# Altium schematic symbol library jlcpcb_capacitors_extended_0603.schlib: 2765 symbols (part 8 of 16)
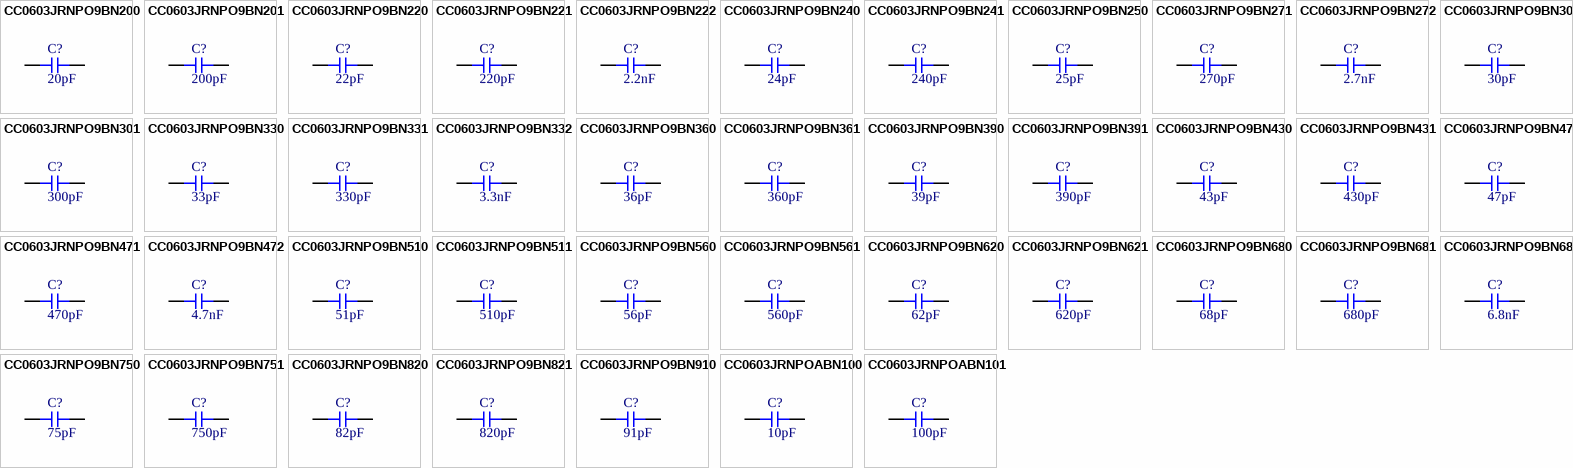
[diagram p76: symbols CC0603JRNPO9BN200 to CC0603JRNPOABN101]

## CC0603JRNPO9BN221
designator C?  Capacitance: 220pF  (hidden comment: *)
Capacitor, Ceramic (MLCC), 220pF, ±5%, 50V, NP0, ±5%, SMD 0603; Manufacturer: YAGEO; Manufacturer Part Number: CC0603JRNPO9BN221
footprint CAP-0603 (0603 (1608M) Capacitor)
pins: 1, 2

## CC0603JRNPO9BN222
designator C?  Capacitance: 2.2nF  (hidden comment: *)
Capacitor, Ceramic (MLCC), 2.2nF, ±5%, 50V, NP0, ±5%, SMD 0603; Manufacturer: YAGEO; Manufacturer Part Number: CC0603JRNPO9BN222
footprint CAP-0603 (0603 (1608M) Capacitor)
pins: 1, 2

## CC0603JRNPO9BN240
designator C?  Capacitance: 24pF  (hidden comment: *)
Capacitor, Ceramic (MLCC), 24pF, ±5%, 50V, NP0, ±5%, SMD 0603; Manufacturer: YAGEO; Manufacturer Part Number: CC0603JRNPO9BN240
footprint CAP-0603 (0603 (1608M) Capacitor)
pins: 1, 2

## CC0603JRNPO9BN241
designator C?  Capacitance: 240pF  (hidden comment: *)
Capacitor, Ceramic (MLCC), 240pF, ±5%, 50V, NP0, ±5%, SMD 0603; Manufacturer: YAGEO; Manufacturer Part Number: CC0603JRNPO9BN241
footprint CAP-0603 (0603 (1608M) Capacitor)
pins: 1, 2

## CC0603JRNPO9BN250
designator C?  Capacitance: 25pF  (hidden comment: *)
Capacitor, Ceramic (MLCC), 25pF, ±5%, 50V, NP0, ±5%, SMD 0603; Manufacturer: YAGEO; Manufacturer Part Number: CC0603JRNPO9BN250
footprint CAP-0603 (0603 (1608M) Capacitor)
pins: 1, 2

## CC0603JRNPO9BN271
designator C?  Capacitance: 270pF  (hidden comment: *)
Capacitor, Ceramic (MLCC), 270pF, ±5%, 50V, NP0, ±5%, SMD 0603; Manufacturer: YAGEO; Manufacturer Part Number: CC0603JRNPO9BN271
footprint CAP-0603 (0603 (1608M) Capacitor)
pins: 1, 2

## CC0603JRNPO9BN272
designator C?  Capacitance: 2.7nF  (hidden comment: *)
Capacitor, Ceramic (MLCC), 2.7nF, ±5%, 50V, NP0, ±5%, SMD 0603; Manufacturer: YAGEO; Manufacturer Part Number: CC0603JRNPO9BN272
footprint CAP-0603 (0603 (1608M) Capacitor)
pins: 1, 2

## CC0603JRNPO9BN300
designator C?  Capacitance: 30pF  (hidden comment: *)
Capacitor, Ceramic (MLCC), 30pF, ±5%, 50V, NP0, ±5%, SMD 0603; Manufacturer: YAGEO; Manufacturer Part Number: CC0603JRNPO9BN300
footprint CAP-0603 (0603 (1608M) Capacitor)
pins: 1, 2

## CC0603JRNPO9BN301
designator C?  Capacitance: 300pF  (hidden comment: *)
Capacitor, Ceramic (MLCC), 300pF, ±5%, 50V, NP0, ±5%, SMD 0603; Manufacturer: YAGEO; Manufacturer Part Number: CC0603JRNPO9BN301
footprint CAP-0603 (0603 (1608M) Capacitor)
pins: 1, 2

## CC0603JRNPO9BN330
designator C?  Capacitance: 33pF  (hidden comment: *)
Capacitor, Ceramic (MLCC), 33pF, ±5%, 50V, NP0, ±5%, SMD 0603; Manufacturer: YAGEO; Manufacturer Part Number: CC0603JRNPO9BN330
footprint CAP-0603 (0603 (1608M) Capacitor)
pins: 1, 2

## CC0603JRNPO9BN331
designator C?  Capacitance: 330pF  (hidden comment: *)
Capacitor, Ceramic (MLCC), 330pF, ±5%, 50V, NP0, ±5%, SMD 0603; Manufacturer: YAGEO; Manufacturer Part Number: CC0603JRNPO9BN331
footprint CAP-0603 (0603 (1608M) Capacitor)
pins: 1, 2

## CC0603JRNPO9BN332
designator C?  Capacitance: 3.3nF  (hidden comment: *)
Capacitor, Ceramic (MLCC), 3.3nF, ±5%, 50V, NP0, ±5%, SMD 0603; Manufacturer: YAGEO; Manufacturer Part Number: CC0603JRNPO9BN332
footprint CAP-0603 (0603 (1608M) Capacitor)
pins: 1, 2

## CC0603JRNPO9BN360
designator C?  Capacitance: 36pF  (hidden comment: *)
Capacitor, Ceramic (MLCC), 36pF, ±5%, 50V, NP0, ±5%, SMD 0603; Manufacturer: YAGEO; Manufacturer Part Number: CC0603JRNPO9BN360
footprint CAP-0603 (0603 (1608M) Capacitor)
pins: 1, 2

## CC0603JRNPO9BN361
designator C?  Capacitance: 360pF  (hidden comment: *)
Capacitor, Ceramic (MLCC), 360pF, ±5%, 50V, NP0, ±5%, SMD 0603; Manufacturer: YAGEO; Manufacturer Part Number: CC0603JRNPO9BN361
footprint CAP-0603 (0603 (1608M) Capacitor)
pins: 1, 2

## CC0603JRNPO9BN390
designator C?  Capacitance: 39pF  (hidden comment: *)
Capacitor, Ceramic (MLCC), 39pF, ±5%, 50V, NP0, ±5%, SMD 0603; Manufacturer: YAGEO; Manufacturer Part Number: CC0603JRNPO9BN390
footprint CAP-0603 (0603 (1608M) Capacitor)
pins: 1, 2

## CC0603JRNPO9BN391
designator C?  Capacitance: 390pF  (hidden comment: *)
Capacitor, Ceramic (MLCC), 390pF, ±5%, 50V, NP0, ±5%, SMD 0603; Manufacturer: YAGEO; Manufacturer Part Number: CC0603JRNPO9BN391
footprint CAP-0603 (0603 (1608M) Capacitor)
pins: 1, 2

## CC0603JRNPO9BN430
designator C?  Capacitance: 43pF  (hidden comment: *)
Capacitor, Ceramic (MLCC), 43pF, ±5%, 50V, NP0, ±5%, SMD 0603; Manufacturer: YAGEO; Manufacturer Part Number: CC0603JRNPO9BN430
footprint CAP-0603 (0603 (1608M) Capacitor)
pins: 1, 2

## CC0603JRNPO9BN431
designator C?  Capacitance: 430pF  (hidden comment: *)
Capacitor, Ceramic (MLCC), 430pF, ±5%, 50V, NP0, ±5%, SMD 0603; Manufacturer: YAGEO; Manufacturer Part Number: CC0603JRNPO9BN431
footprint CAP-0603 (0603 (1608M) Capacitor)
pins: 1, 2

## CC0603JRNPO9BN470
designator C?  Capacitance: 47pF  (hidden comment: *)
Capacitor, Ceramic (MLCC), 47pF, ±5%, 50V, NP0, ±5%, SMD 0603; Manufacturer: YAGEO; Manufacturer Part Number: CC0603JRNPO9BN470
footprint CAP-0603 (0603 (1608M) Capacitor)
pins: 1, 2

## CC0603JRNPO9BN471
designator C?  Capacitance: 470pF  (hidden comment: *)
Capacitor, Ceramic (MLCC), 470pF, ±5%, 50V, NP0, ±5%, SMD 0603; Manufacturer: YAGEO; Manufacturer Part Number: CC0603JRNPO9BN471
footprint CAP-0603 (0603 (1608M) Capacitor)
pins: 1, 2

## CC0603JRNPO9BN472
designator C?  Capacitance: 4.7nF  (hidden comment: *)
Capacitor, Ceramic (MLCC), 4.7nF, ±5%, 50V, NP0, ±5%, SMD 0603; Manufacturer: YAGEO; Manufacturer Part Number: CC0603JRNPO9BN472
footprint CAP-0603 (0603 (1608M) Capacitor)
pins: 1, 2

## CC0603JRNPO9BN510
designator C?  Capacitance: 51pF  (hidden comment: *)
Capacitor, Ceramic (MLCC), 51pF, ±5%, 50V, NP0, ±5%, SMD 0603; Manufacturer: YAGEO; Manufacturer Part Number: CC0603JRNPO9BN510
footprint CAP-0603 (0603 (1608M) Capacitor)
pins: 1, 2

## CC0603JRNPO9BN511
designator C?  Capacitance: 510pF  (hidden comment: *)
Capacitor, Ceramic (MLCC), 510pF, ±5%, 50V, NP0, ±5%, SMD 0603; Manufacturer: YAGEO; Manufacturer Part Number: CC0603JRNPO9BN511
footprint CAP-0603 (0603 (1608M) Capacitor)
pins: 1, 2

## CC0603JRNPO9BN560
designator C?  Capacitance: 56pF  (hidden comment: *)
Capacitor, Ceramic (MLCC), 56pF, ±5%, 50V, NP0, ±5%, SMD 0603; Manufacturer: YAGEO; Manufacturer Part Number: CC0603JRNPO9BN560
footprint CAP-0603 (0603 (1608M) Capacitor)
pins: 1, 2

## CC0603JRNPO9BN561
designator C?  Capacitance: 560pF  (hidden comment: *)
Capacitor, Ceramic (MLCC), 560pF, ±5%, 50V, NP0, ±5%, SMD 0603; Manufacturer: YAGEO; Manufacturer Part Number: CC0603JRNPO9BN561
footprint CAP-0603 (0603 (1608M) Capacitor)
pins: 1, 2

## CC0603JRNPO9BN620
designator C?  Capacitance: 62pF  (hidden comment: *)
Capacitor, Ceramic (MLCC), 62pF, ±5%, 50V, NP0, ±5%, SMD 0603; Manufacturer: YAGEO; Manufacturer Part Number: CC0603JRNPO9BN620
footprint CAP-0603 (0603 (1608M) Capacitor)
pins: 1, 2

## CC0603JRNPO9BN621
designator C?  Capacitance: 620pF  (hidden comment: *)
Capacitor, Ceramic (MLCC), 620pF, ±5%, 50V, NP0, ±5%, SMD 0603; Manufacturer: YAGEO; Manufacturer Part Number: CC0603JRNPO9BN621
footprint CAP-0603 (0603 (1608M) Capacitor)
pins: 1, 2

## CC0603JRNPO9BN680
designator C?  Capacitance: 68pF  (hidden comment: *)
Capacitor, Ceramic (MLCC), 68pF, ±5%, 50V, NP0, ±5%, SMD 0603; Manufacturer: YAGEO; Manufacturer Part Number: CC0603JRNPO9BN680
footprint CAP-0603 (0603 (1608M) Capacitor)
pins: 1, 2

## CC0603JRNPO9BN681
designator C?  Capacitance: 680pF  (hidden comment: *)
Capacitor, Ceramic (MLCC), 680pF, ±5%, 50V, NP0, ±5%, SMD 0603; Manufacturer: YAGEO; Manufacturer Part Number: CC0603JRNPO9BN681
footprint CAP-0603 (0603 (1608M) Capacitor)
pins: 1, 2

## CC0603JRNPO9BN682
designator C?  Capacitance: 6.8nF  (hidden comment: *)
Capacitor, Ceramic (MLCC), 6.8nF, ±5%, 50V, NP0, ±5%, SMD 0603; Manufacturer: YAGEO; Manufacturer Part Number: CC0603JRNPO9BN682
footprint CAP-0603 (0603 (1608M) Capacitor)
pins: 1, 2

## CC0603JRNPO9BN750
designator C?  Capacitance: 75pF  (hidden comment: *)
Capacitor, Ceramic (MLCC), 75pF, ±5%, 50V, NP0, ±5%, SMD 0603; Manufacturer: YAGEO; Manufacturer Part Number: CC0603JRNPO9BN750
footprint CAP-0603 (0603 (1608M) Capacitor)
pins: 1, 2

## CC0603JRNPO9BN751
designator C?  Capacitance: 750pF  (hidden comment: *)
Capacitor, Ceramic (MLCC), 750pF, ±5%, 50V, NP0, ±5%, SMD 0603; Manufacturer: YAGEO; Manufacturer Part Number: CC0603JRNPO9BN751
footprint CAP-0603 (0603 (1608M) Capacitor)
pins: 1, 2

## CC0603JRNPO9BN820
designator C?  Capacitance: 82pF  (hidden comment: *)
Capacitor, Ceramic (MLCC), 82pF, ±5%, 50V, NP0, ±5%, SMD 0603; Manufacturer: YAGEO; Manufacturer Part Number: CC0603JRNPO9BN820
footprint CAP-0603 (0603 (1608M) Capacitor)
pins: 1, 2

## CC0603JRNPO9BN821
designator C?  Capacitance: 820pF  (hidden comment: *)
Capacitor, Ceramic (MLCC), 820pF, ±5%, 50V, NP0, ±5%, SMD 0603; Manufacturer: YAGEO; Manufacturer Part Number: CC0603JRNPO9BN821
footprint CAP-0603 (0603 (1608M) Capacitor)
pins: 1, 2

## CC0603JRNPO9BN910
designator C?  Capacitance: 91pF  (hidden comment: *)
Capacitor, Ceramic (MLCC), 91pF, ±5%, 50V, NP0, ±5%, SMD 0603; Manufacturer: YAGEO; Manufacturer Part Number: CC0603JRNPO9BN910
footprint CAP-0603 (0603 (1608M) Capacitor)
pins: 1, 2

## CC0603JRNPOABN100
designator C?  Capacitance: 10pF  (hidden comment: *)
Capacitor, Ceramic (MLCC), 10pF, ±5%, 200V, NP0, ±5%, SMD 0603; Manufacturer: YAGEO; Manufacturer Part Number: CC0603JRNPOABN100
footprint CAP-0603 (0603 (1608M) Capacitor)
pins: 1, 2

## CC0603JRNPOABN101
designator C?  Capacitance: 100pF  (hidden comment: *)
Capacitor, Ceramic (MLCC), 100pF, ±5%, 200V, NP0, ±5%, SMD 0603; Manufacturer: YAGEO; Manufacturer Part Number: CC0603JRNPOABN101
footprint CAP-0603 (0603 (1608M) Capacitor)
pins: 1, 2

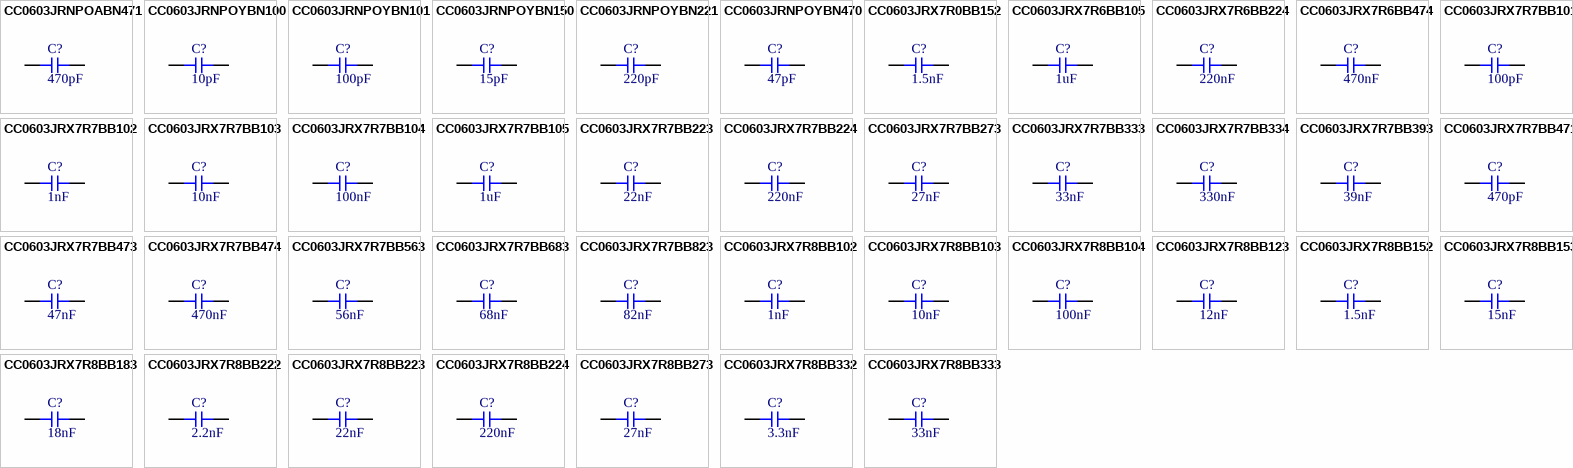
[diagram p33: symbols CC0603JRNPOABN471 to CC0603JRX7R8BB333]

## CC0603JRNPOABN471
designator C?  Capacitance: 470pF  (hidden comment: *)
Capacitor, Ceramic (MLCC), 470pF, ±5%, 200V, NP0, ±5%, SMD 0603; Manufacturer: YAGEO; Manufacturer Part Number: CC0603JRNPOABN471
footprint CAP-0603 (0603 (1608M) Capacitor)
pins: 1, 2

## CC0603JRNPOYBN100
designator C?  Capacitance: 10pF  (hidden comment: *)
Capacitor, Ceramic (MLCC), 10pF, ±5%, 250V, NP0, ±5%, SMD 0603; Manufacturer: YAGEO; Manufacturer Part Number: CC0603JRNPOYBN100
footprint CAP-0603 (0603 (1608M) Capacitor)
pins: 1, 2

## CC0603JRNPOYBN101
designator C?  Capacitance: 100pF  (hidden comment: *)
Capacitor, Ceramic (MLCC), 100pF, ±5%, 250V, NP0, ±5%, SMD 0603; Manufacturer: YAGEO; Manufacturer Part Number: CC0603JRNPOYBN101
footprint CAP-0603 (0603 (1608M) Capacitor)
pins: 1, 2

## CC0603JRNPOYBN150
designator C?  Capacitance: 15pF  (hidden comment: *)
Capacitor, Ceramic (MLCC), 15pF, ±5%, 250V, NP0, ±5%, SMD 0603; Manufacturer: YAGEO; Manufacturer Part Number: CC0603JRNPOYBN150
footprint CAP-0603 (0603 (1608M) Capacitor)
pins: 1, 2

## CC0603JRNPOYBN221
designator C?  Capacitance: 220pF  (hidden comment: *)
Capacitor, Ceramic (MLCC), 220pF, ±5%, 250V, NP0, ±5%, SMD 0603; Manufacturer: YAGEO; Manufacturer Part Number: CC0603JRNPOYBN221
footprint CAP-0603 (0603 (1608M) Capacitor)
pins: 1, 2

## CC0603JRNPOYBN470
designator C?  Capacitance: 47pF  (hidden comment: *)
Capacitor, Ceramic (MLCC), 47pF, ±5%, 250V, NP0, ±5%, SMD 0603; Manufacturer: YAGEO; Manufacturer Part Number: CC0603JRNPOYBN470
footprint CAP-0603 (0603 (1608M) Capacitor)
pins: 1, 2

## CC0603JRX7R0BB152
designator C?  Capacitance: 1.5nF  (hidden comment: *)
Capacitor, Ceramic (MLCC), 1.5nF, ±5%, 100V, X7R, ±5%, SMD 0603; Manufacturer: YAGEO; Manufacturer Part Number: CC0603JRX7R0BB152
footprint CAP-0603 (0603 (1608M) Capacitor)
pins: 1, 2

## CC0603JRX7R6BB105
designator C?  Capacitance: 1uF  (hidden comment: *)
Capacitor, Ceramic (MLCC), 1uF, ±5%, 10V, X7R, ±5%, SMD 0603; Manufacturer: YAGEO; Manufacturer Part Number: CC0603JRX7R6BB105
footprint CAP-0603 (0603 (1608M) Capacitor)
pins: 1, 2

## CC0603JRX7R6BB224
designator C?  Capacitance: 220nF  (hidden comment: *)
Capacitor, Ceramic (MLCC), 220nF, ±5%, 10V, X7R, ±5%, SMD 0603; Manufacturer: YAGEO; Manufacturer Part Number: CC0603JRX7R6BB224
footprint CAP-0603 (0603 (1608M) Capacitor)
pins: 1, 2

## CC0603JRX7R6BB474
designator C?  Capacitance: 470nF  (hidden comment: *)
Capacitor, Ceramic (MLCC), 470nF, ±5%, 10V, X7R, ±5%, SMD 0603; Manufacturer: YAGEO; Manufacturer Part Number: CC0603JRX7R6BB474
footprint CAP-0603 (0603 (1608M) Capacitor)
pins: 1, 2

## CC0603JRX7R7BB101
designator C?  Capacitance: 100pF  (hidden comment: *)
Capacitor, Ceramic (MLCC), 100pF, ±5%, 16V, X7R, ±5%, SMD 0603; Manufacturer: YAGEO; Manufacturer Part Number: CC0603JRX7R7BB101
footprint CAP-0603 (0603 (1608M) Capacitor)
pins: 1, 2

## CC0603JRX7R7BB102
designator C?  Capacitance: 1nF  (hidden comment: *)
Capacitor, Ceramic (MLCC), 1nF, ±5%, 16V, X7R, ±5%, SMD 0603; Manufacturer: YAGEO; Manufacturer Part Number: CC0603JRX7R7BB102
footprint CAP-0603 (0603 (1608M) Capacitor)
pins: 1, 2

## CC0603JRX7R7BB103
designator C?  Capacitance: 10nF  (hidden comment: *)
Capacitor, Ceramic (MLCC), 10nF, ±5%, 16V, X7R, ±5%, SMD 0603; Manufacturer: YAGEO; Manufacturer Part Number: CC0603JRX7R7BB103
footprint CAP-0603 (0603 (1608M) Capacitor)
pins: 1, 2

## CC0603JRX7R7BB104
designator C?  Capacitance: 100nF  (hidden comment: *)
Capacitor, Ceramic (MLCC), 100nF, ±5%, 16V, X7R, ±5%, SMD 0603; Manufacturer: YAGEO; Manufacturer Part Number: CC0603JRX7R7BB104
footprint CAP-0603 (0603 (1608M) Capacitor)
pins: 1, 2

## CC0603JRX7R7BB105
designator C?  Capacitance: 1uF  (hidden comment: *)
Capacitor, Ceramic (MLCC), 1uF, ±5%, 16V, X7R, ±5%, SMD 0603; Manufacturer: YAGEO; Manufacturer Part Number: CC0603JRX7R7BB105
footprint CAP-0603 (0603 (1608M) Capacitor)
pins: 1, 2

## CC0603JRX7R7BB223
designator C?  Capacitance: 22nF  (hidden comment: *)
Capacitor, Ceramic (MLCC), 22nF, ±5%, 16V, X7R, ±5%, SMD 0603; Manufacturer: YAGEO; Manufacturer Part Number: CC0603JRX7R7BB223
footprint CAP-0603 (0603 (1608M) Capacitor)
pins: 1, 2

## CC0603JRX7R7BB224
designator C?  Capacitance: 220nF  (hidden comment: *)
Capacitor, Ceramic (MLCC), 220nF, ±5%, 16V, X7R, ±5%, SMD 0603; Manufacturer: YAGEO; Manufacturer Part Number: CC0603JRX7R7BB224
footprint CAP-0603 (0603 (1608M) Capacitor)
pins: 1, 2

## CC0603JRX7R7BB273
designator C?  Capacitance: 27nF  (hidden comment: *)
Capacitor, Ceramic (MLCC), 27nF, ±5%, 16V, X7R, ±5%, SMD 0603; Manufacturer: YAGEO; Manufacturer Part Number: CC0603JRX7R7BB273
footprint CAP-0603 (0603 (1608M) Capacitor)
pins: 1, 2

## CC0603JRX7R7BB333
designator C?  Capacitance: 33nF  (hidden comment: *)
Capacitor, Ceramic (MLCC), 33nF, ±5%, 16V, X7R, ±5%, SMD 0603; Manufacturer: YAGEO; Manufacturer Part Number: CC0603JRX7R7BB333
footprint CAP-0603 (0603 (1608M) Capacitor)
pins: 1, 2

## CC0603JRX7R7BB334
designator C?  Capacitance: 330nF  (hidden comment: *)
Capacitor, Ceramic (MLCC), 330nF, ±5%, 16V, X7R, ±5%, SMD 0603; Manufacturer: YAGEO; Manufacturer Part Number: CC0603JRX7R7BB334
footprint CAP-0603 (0603 (1608M) Capacitor)
pins: 1, 2

## CC0603JRX7R7BB393
designator C?  Capacitance: 39nF  (hidden comment: *)
Capacitor, Ceramic (MLCC), 39nF, ±5%, 16V, X7R, ±5%, SMD 0603; Manufacturer: YAGEO; Manufacturer Part Number: CC0603JRX7R7BB393
footprint CAP-0603 (0603 (1608M) Capacitor)
pins: 1, 2

## CC0603JRX7R7BB471
designator C?  Capacitance: 470pF  (hidden comment: *)
Capacitor, Ceramic (MLCC), 470pF, ±5%, 16V, X7R, ±5%, SMD 0603; Manufacturer: YAGEO; Manufacturer Part Number: CC0603JRX7R7BB471
footprint CAP-0603 (0603 (1608M) Capacitor)
pins: 1, 2

## CC0603JRX7R7BB473
designator C?  Capacitance: 47nF  (hidden comment: *)
Capacitor, Ceramic (MLCC), 47nF, ±5%, 16V, X7R, ±5%, SMD 0603; Manufacturer: YAGEO; Manufacturer Part Number: CC0603JRX7R7BB473
footprint CAP-0603 (0603 (1608M) Capacitor)
pins: 1, 2

## CC0603JRX7R7BB474
designator C?  Capacitance: 470nF  (hidden comment: *)
Capacitor, Ceramic (MLCC), 470nF, ±5%, 16V, X7R, ±5%, SMD 0603; Manufacturer: YAGEO; Manufacturer Part Number: CC0603JRX7R7BB474
footprint CAP-0603 (0603 (1608M) Capacitor)
pins: 1, 2

## CC0603JRX7R7BB563
designator C?  Capacitance: 56nF  (hidden comment: *)
Capacitor, Ceramic (MLCC), 56nF, ±5%, 16V, X7R, ±5%, SMD 0603; Manufacturer: YAGEO; Manufacturer Part Number: CC0603JRX7R7BB563
footprint CAP-0603 (0603 (1608M) Capacitor)
pins: 1, 2

## CC0603JRX7R7BB683
designator C?  Capacitance: 68nF  (hidden comment: *)
Capacitor, Ceramic (MLCC), 68nF, ±5%, 16V, X7R, ±5%, SMD 0603; Manufacturer: YAGEO; Manufacturer Part Number: CC0603JRX7R7BB683
footprint CAP-0603 (0603 (1608M) Capacitor)
pins: 1, 2

## CC0603JRX7R7BB823
designator C?  Capacitance: 82nF  (hidden comment: *)
Capacitor, Ceramic (MLCC), 82nF, ±5%, 16V, X7R, ±5%, SMD 0603; Manufacturer: YAGEO; Manufacturer Part Number: CC0603JRX7R7BB823
footprint CAP-0603 (0603 (1608M) Capacitor)
pins: 1, 2

## CC0603JRX7R8BB102
designator C?  Capacitance: 1nF  (hidden comment: *)
Capacitor, Ceramic (MLCC), 1nF, ±5%, 25V, X7R, ±5%, SMD 0603; Manufacturer: YAGEO; Manufacturer Part Number: CC0603JRX7R8BB102
footprint CAP-0603 (0603 (1608M) Capacitor)
pins: 1, 2

## CC0603JRX7R8BB103
designator C?  Capacitance: 10nF  (hidden comment: *)
Capacitor, Ceramic (MLCC), 10nF, ±5%, 25V, X7R, ±5%, SMD 0603; Manufacturer: YAGEO; Manufacturer Part Number: CC0603JRX7R8BB103
footprint CAP-0603 (0603 (1608M) Capacitor)
pins: 1, 2

## CC0603JRX7R8BB104
designator C?  Capacitance: 100nF  (hidden comment: *)
Capacitor, Ceramic (MLCC), 100nF, ±5%, 25V, X7R, ±5%, SMD 0603; Manufacturer: YAGEO; Manufacturer Part Number: CC0603JRX7R8BB104
footprint CAP-0603 (0603 (1608M) Capacitor)
pins: 1, 2

## CC0603JRX7R8BB123
designator C?  Capacitance: 12nF  (hidden comment: *)
Capacitor, Ceramic (MLCC), 12nF, ±5%, 25V, X7R, ±5%, SMD 0603; Manufacturer: YAGEO; Manufacturer Part Number: CC0603JRX7R8BB123
footprint CAP-0603 (0603 (1608M) Capacitor)
pins: 1, 2

## CC0603JRX7R8BB152
designator C?  Capacitance: 1.5nF  (hidden comment: *)
Capacitor, Ceramic (MLCC), 1.5nF, ±5%, 25V, X7R, ±5%, SMD 0603; Manufacturer: YAGEO; Manufacturer Part Number: CC0603JRX7R8BB152
footprint CAP-0603 (0603 (1608M) Capacitor)
pins: 1, 2

## CC0603JRX7R8BB153
designator C?  Capacitance: 15nF  (hidden comment: *)
Capacitor, Ceramic (MLCC), 15nF, ±5%, 25V, X7R, ±5%, SMD 0603; Manufacturer: YAGEO; Manufacturer Part Number: CC0603JRX7R8BB153
footprint CAP-0603 (0603 (1608M) Capacitor)
pins: 1, 2

## CC0603JRX7R8BB183
designator C?  Capacitance: 18nF  (hidden comment: *)
Capacitor, Ceramic (MLCC), 18nF, ±5%, 25V, X7R, ±5%, SMD 0603; Manufacturer: YAGEO; Manufacturer Part Number: CC0603JRX7R8BB183
footprint CAP-0603 (0603 (1608M) Capacitor)
pins: 1, 2

## CC0603JRX7R8BB222
designator C?  Capacitance: 2.2nF  (hidden comment: *)
Capacitor, Ceramic (MLCC), 2.2nF, ±5%, 25V, X7R, ±5%, SMD 0603; Manufacturer: YAGEO; Manufacturer Part Number: CC0603JRX7R8BB222
footprint CAP-0603 (0603 (1608M) Capacitor)
pins: 1, 2

## CC0603JRX7R8BB223
designator C?  Capacitance: 22nF  (hidden comment: *)
Capacitor, Ceramic (MLCC), 22nF, ±5%, 25V, X7R, ±5%, SMD 0603; Manufacturer: YAGEO; Manufacturer Part Number: CC0603JRX7R8BB223
footprint CAP-0603 (0603 (1608M) Capacitor)
pins: 1, 2

## CC0603JRX7R8BB224
designator C?  Capacitance: 220nF  (hidden comment: *)
Capacitor, Ceramic (MLCC), 220nF, ±5%, 25V, X7R, ±5%, SMD 0603; Manufacturer: YAGEO; Manufacturer Part Number: CC0603JRX7R8BB224
footprint CAP-0603 (0603 (1608M) Capacitor)
pins: 1, 2

## CC0603JRX7R8BB273
designator C?  Capacitance: 27nF  (hidden comment: *)
Capacitor, Ceramic (MLCC), 27nF, ±5%, 25V, X7R, ±5%, SMD 0603; Manufacturer: YAGEO; Manufacturer Part Number: CC0603JRX7R8BB273
footprint CAP-0603 (0603 (1608M) Capacitor)
pins: 1, 2

## CC0603JRX7R8BB332
designator C?  Capacitance: 3.3nF  (hidden comment: *)
Capacitor, Ceramic (MLCC), 3.3nF, ±5%, 25V, X7R, ±5%, SMD 0603; Manufacturer: YAGEO; Manufacturer Part Number: CC0603JRX7R8BB332
footprint CAP-0603 (0603 (1608M) Capacitor)
pins: 1, 2

## CC0603JRX7R8BB333
designator C?  Capacitance: 33nF  (hidden comment: *)
Capacitor, Ceramic (MLCC), 33nF, ±5%, 25V, X7R, ±5%, SMD 0603; Manufacturer: YAGEO; Manufacturer Part Number: CC0603JRX7R8BB333
footprint CAP-0603 (0603 (1608M) Capacitor)
pins: 1, 2

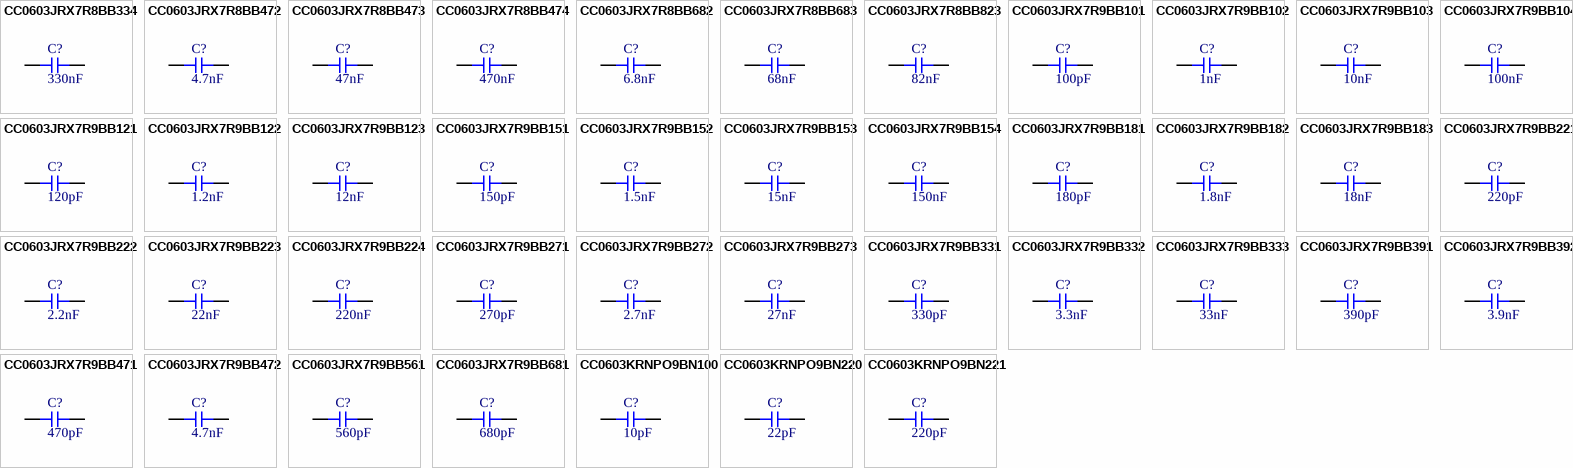
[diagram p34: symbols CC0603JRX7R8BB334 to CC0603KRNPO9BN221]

## CC0603JRX7R8BB334
designator C?  Capacitance: 330nF  (hidden comment: *)
Capacitor, Ceramic (MLCC), 330nF, ±5%, 25V, X7R, ±5%, SMD 0603; Manufacturer: YAGEO; Manufacturer Part Number: CC0603JRX7R8BB334
footprint CAP-0603 (0603 (1608M) Capacitor)
pins: 1, 2

## CC0603JRX7R8BB472
designator C?  Capacitance: 4.7nF  (hidden comment: *)
Capacitor, Ceramic (MLCC), 4.7nF, ±5%, 25V, X7R, ±5%, SMD 0603; Manufacturer: YAGEO; Manufacturer Part Number: CC0603JRX7R8BB472
footprint CAP-0603 (0603 (1608M) Capacitor)
pins: 1, 2

## CC0603JRX7R8BB473
designator C?  Capacitance: 47nF  (hidden comment: *)
Capacitor, Ceramic (MLCC), 47nF, ±5%, 25V, X7R, ±5%, SMD 0603; Manufacturer: YAGEO; Manufacturer Part Number: CC0603JRX7R8BB473
footprint CAP-0603 (0603 (1608M) Capacitor)
pins: 1, 2

## CC0603JRX7R8BB474
designator C?  Capacitance: 470nF  (hidden comment: *)
Capacitor, Ceramic (MLCC), 470nF, ±5%, 25V, X7R, ±5%, SMD 0603; Manufacturer: YAGEO; Manufacturer Part Number: CC0603JRX7R8BB474
footprint CAP-0603 (0603 (1608M) Capacitor)
pins: 1, 2

## CC0603JRX7R8BB682
designator C?  Capacitance: 6.8nF  (hidden comment: *)
Capacitor, Ceramic (MLCC), 6.8nF, ±5%, 25V, X7R, ±5%, SMD 0603; Manufacturer: YAGEO; Manufacturer Part Number: CC0603JRX7R8BB682
footprint CAP-0603 (0603 (1608M) Capacitor)
pins: 1, 2

## CC0603JRX7R8BB683
designator C?  Capacitance: 68nF  (hidden comment: *)
Capacitor, Ceramic (MLCC), 68nF, ±5%, 25V, X7R, ±5%, SMD 0603; Manufacturer: YAGEO; Manufacturer Part Number: CC0603JRX7R8BB683
footprint CAP-0603 (0603 (1608M) Capacitor)
pins: 1, 2

## CC0603JRX7R8BB823
designator C?  Capacitance: 82nF  (hidden comment: *)
Capacitor, Ceramic (MLCC), 82nF, ±5%, 25V, X7R, ±5%, SMD 0603; Manufacturer: YAGEO; Manufacturer Part Number: CC0603JRX7R8BB823
footprint CAP-0603 (0603 (1608M) Capacitor)
pins: 1, 2

## CC0603JRX7R9BB101
designator C?  Capacitance: 100pF  (hidden comment: *)
Capacitor, Ceramic (MLCC), 100pF, ±5%, 50V, X7R, ±5%, SMD 0603; Manufacturer: YAGEO; Manufacturer Part Number: CC0603JRX7R9BB101
footprint CAP-0603 (0603 (1608M) Capacitor)
pins: 1, 2

## CC0603JRX7R9BB102
designator C?  Capacitance: 1nF  (hidden comment: *)
Capacitor, Ceramic (MLCC), 1nF, ±5%, 50V, X7R, ±5%, SMD 0603; Manufacturer: YAGEO; Manufacturer Part Number: CC0603JRX7R9BB102
footprint CAP-0603 (0603 (1608M) Capacitor)
pins: 1, 2

## CC0603JRX7R9BB103
designator C?  Capacitance: 10nF  (hidden comment: *)
Capacitor, Ceramic (MLCC), 10nF, ±5%, 50V, X7R, ±5%, SMD 0603; Manufacturer: YAGEO; Manufacturer Part Number: CC0603JRX7R9BB103
footprint CAP-0603 (0603 (1608M) Capacitor)
pins: 1, 2

## CC0603JRX7R9BB104
designator C?  Capacitance: 100nF  (hidden comment: *)
Capacitor, Ceramic (MLCC), 100nF, ±5%, 50V, X7R, ±5%, SMD 0603; Manufacturer: YAGEO; Manufacturer Part Number: CC0603JRX7R9BB104
footprint CAP-0603 (0603 (1608M) Capacitor)
pins: 1, 2

## CC0603JRX7R9BB121
designator C?  Capacitance: 120pF  (hidden comment: *)
Capacitor, Ceramic (MLCC), 120pF, ±5%, 50V, X7R, ±5%, SMD 0603; Manufacturer: YAGEO; Manufacturer Part Number: CC0603JRX7R9BB121
footprint CAP-0603 (0603 (1608M) Capacitor)
pins: 1, 2

## CC0603JRX7R9BB122
designator C?  Capacitance: 1.2nF  (hidden comment: *)
Capacitor, Ceramic (MLCC), 1.2nF, ±5%, 50V, X7R, ±5%, SMD 0603; Manufacturer: YAGEO; Manufacturer Part Number: CC0603JRX7R9BB122
footprint CAP-0603 (0603 (1608M) Capacitor)
pins: 1, 2

## CC0603JRX7R9BB123
designator C?  Capacitance: 12nF  (hidden comment: *)
Capacitor, Ceramic (MLCC), 12nF, ±5%, 50V, X7R, ±5%, SMD 0603; Manufacturer: YAGEO; Manufacturer Part Number: CC0603JRX7R9BB123
footprint CAP-0603 (0603 (1608M) Capacitor)
pins: 1, 2

## CC0603JRX7R9BB151
designator C?  Capacitance: 150pF  (hidden comment: *)
Capacitor, Ceramic (MLCC), 150pF, ±5%, 50V, X7R, ±5%, SMD 0603; Manufacturer: YAGEO; Manufacturer Part Number: CC0603JRX7R9BB151
footprint CAP-0603 (0603 (1608M) Capacitor)
pins: 1, 2

## CC0603JRX7R9BB152
designator C?  Capacitance: 1.5nF  (hidden comment: *)
Capacitor, Ceramic (MLCC), 1.5nF, ±5%, 50V, X7R, ±5%, SMD 0603; Manufacturer: YAGEO; Manufacturer Part Number: CC0603JRX7R9BB152
footprint CAP-0603 (0603 (1608M) Capacitor)
pins: 1, 2

## CC0603JRX7R9BB153
designator C?  Capacitance: 15nF  (hidden comment: *)
Capacitor, Ceramic (MLCC), 15nF, ±5%, 50V, X7R, ±5%, SMD 0603; Manufacturer: YAGEO; Manufacturer Part Number: CC0603JRX7R9BB153
footprint CAP-0603 (0603 (1608M) Capacitor)
pins: 1, 2

## CC0603JRX7R9BB154
designator C?  Capacitance: 150nF  (hidden comment: *)
Capacitor, Ceramic (MLCC), 150nF, ±5%, 50V, X7R, ±5%, SMD 0603; Manufacturer: YAGEO; Manufacturer Part Number: CC0603JRX7R9BB154
footprint CAP-0603 (0603 (1608M) Capacitor)
pins: 1, 2

## CC0603JRX7R9BB181
designator C?  Capacitance: 180pF  (hidden comment: *)
Capacitor, Ceramic (MLCC), 180pF, ±5%, 50V, X7R, ±5%, SMD 0603; Manufacturer: YAGEO; Manufacturer Part Number: CC0603JRX7R9BB181
footprint CAP-0603 (0603 (1608M) Capacitor)
pins: 1, 2

## CC0603JRX7R9BB182
designator C?  Capacitance: 1.8nF  (hidden comment: *)
Capacitor, Ceramic (MLCC), 1.8nF, ±5%, 50V, X7R, ±5%, SMD 0603; Manufacturer: YAGEO; Manufacturer Part Number: CC0603JRX7R9BB182
footprint CAP-0603 (0603 (1608M) Capacitor)
pins: 1, 2

## CC0603JRX7R9BB183
designator C?  Capacitance: 18nF  (hidden comment: *)
Capacitor, Ceramic (MLCC), 18nF, ±5%, 50V, X7R, ±5%, SMD 0603; Manufacturer: YAGEO; Manufacturer Part Number: CC0603JRX7R9BB183
footprint CAP-0603 (0603 (1608M) Capacitor)
pins: 1, 2

## CC0603JRX7R9BB221
designator C?  Capacitance: 220pF  (hidden comment: *)
Capacitor, Ceramic (MLCC), 220pF, ±5%, 50V, X7R, ±5%, SMD 0603; Manufacturer: YAGEO; Manufacturer Part Number: CC0603JRX7R9BB221
footprint CAP-0603 (0603 (1608M) Capacitor)
pins: 1, 2

## CC0603JRX7R9BB222
designator C?  Capacitance: 2.2nF  (hidden comment: *)
Capacitor, Ceramic (MLCC), 2.2nF, ±5%, 50V, X7R, ±5%, SMD 0603; Manufacturer: YAGEO; Manufacturer Part Number: CC0603JRX7R9BB222
footprint CAP-0603 (0603 (1608M) Capacitor)
pins: 1, 2

## CC0603JRX7R9BB223
designator C?  Capacitance: 22nF  (hidden comment: *)
Capacitor, Ceramic (MLCC), 22nF, ±5%, 50V, X7R, ±5%, SMD 0603; Manufacturer: YAGEO; Manufacturer Part Number: CC0603JRX7R9BB223
footprint CAP-0603 (0603 (1608M) Capacitor)
pins: 1, 2

## CC0603JRX7R9BB224
designator C?  Capacitance: 220nF  (hidden comment: *)
Capacitor, Ceramic (MLCC), 220nF, ±5%, 50V, X7R, ±5%, SMD 0603; Manufacturer: YAGEO; Manufacturer Part Number: CC0603JRX7R9BB224
footprint CAP-0603 (0603 (1608M) Capacitor)
pins: 1, 2

## CC0603JRX7R9BB271
designator C?  Capacitance: 270pF  (hidden comment: *)
Capacitor, Ceramic (MLCC), 270pF, ±5%, 50V, X7R, ±5%, SMD 0603; Manufacturer: YAGEO; Manufacturer Part Number: CC0603JRX7R9BB271
footprint CAP-0603 (0603 (1608M) Capacitor)
pins: 1, 2

## CC0603JRX7R9BB272
designator C?  Capacitance: 2.7nF  (hidden comment: *)
Capacitor, Ceramic (MLCC), 2.7nF, ±5%, 50V, X7R, ±5%, SMD 0603; Manufacturer: YAGEO; Manufacturer Part Number: CC0603JRX7R9BB272
footprint CAP-0603 (0603 (1608M) Capacitor)
pins: 1, 2

## CC0603JRX7R9BB273
designator C?  Capacitance: 27nF  (hidden comment: *)
Capacitor, Ceramic (MLCC), 27nF, ±5%, 50V, X7R, ±5%, SMD 0603; Manufacturer: YAGEO; Manufacturer Part Number: CC0603JRX7R9BB273
footprint CAP-0603 (0603 (1608M) Capacitor)
pins: 1, 2

## CC0603JRX7R9BB331
designator C?  Capacitance: 330pF  (hidden comment: *)
Capacitor, Ceramic (MLCC), 330pF, ±5%, 50V, X7R, ±5%, SMD 0603; Manufacturer: YAGEO; Manufacturer Part Number: CC0603JRX7R9BB331
footprint CAP-0603 (0603 (1608M) Capacitor)
pins: 1, 2

## CC0603JRX7R9BB332
designator C?  Capacitance: 3.3nF  (hidden comment: *)
Capacitor, Ceramic (MLCC), 3.3nF, ±5%, 50V, X7R, ±5%, SMD 0603; Manufacturer: YAGEO; Manufacturer Part Number: CC0603JRX7R9BB332
footprint CAP-0603 (0603 (1608M) Capacitor)
pins: 1, 2

## CC0603JRX7R9BB333
designator C?  Capacitance: 33nF  (hidden comment: *)
Capacitor, Ceramic (MLCC), 33nF, ±5%, 50V, X7R, ±5%, SMD 0603; Manufacturer: YAGEO; Manufacturer Part Number: CC0603JRX7R9BB333
footprint CAP-0603 (0603 (1608M) Capacitor)
pins: 1, 2

## CC0603JRX7R9BB391
designator C?  Capacitance: 390pF  (hidden comment: *)
Capacitor, Ceramic (MLCC), 390pF, ±5%, 50V, X7R, ±5%, SMD 0603; Manufacturer: YAGEO; Manufacturer Part Number: CC0603JRX7R9BB391
footprint CAP-0603 (0603 (1608M) Capacitor)
pins: 1, 2

## CC0603JRX7R9BB392
designator C?  Capacitance: 3.9nF  (hidden comment: *)
Capacitor, Ceramic (MLCC), 3.9nF, ±5%, 50V, X7R, ±5%, SMD 0603; Manufacturer: YAGEO; Manufacturer Part Number: CC0603JRX7R9BB392
footprint CAP-0603 (0603 (1608M) Capacitor)
pins: 1, 2

## CC0603JRX7R9BB471
designator C?  Capacitance: 470pF  (hidden comment: *)
Capacitor, Ceramic (MLCC), 470pF, ±5%, 50V, X7R, ±5%, SMD 0603; Manufacturer: YAGEO; Manufacturer Part Number: CC0603JRX7R9BB471
footprint CAP-0603 (0603 (1608M) Capacitor)
pins: 1, 2

## CC0603JRX7R9BB472
designator C?  Capacitance: 4.7nF  (hidden comment: *)
Capacitor, Ceramic (MLCC), 4.7nF, ±5%, 50V, X7R, ±5%, SMD 0603; Manufacturer: YAGEO; Manufacturer Part Number: CC0603JRX7R9BB472
footprint CAP-0603 (0603 (1608M) Capacitor)
pins: 1, 2

## CC0603JRX7R9BB561
designator C?  Capacitance: 560pF  (hidden comment: *)
Capacitor, Ceramic (MLCC), 560pF, ±5%, 50V, X7R, ±5%, SMD 0603; Manufacturer: YAGEO; Manufacturer Part Number: CC0603JRX7R9BB561
footprint CAP-0603 (0603 (1608M) Capacitor)
pins: 1, 2

## CC0603JRX7R9BB681
designator C?  Capacitance: 680pF  (hidden comment: *)
Capacitor, Ceramic (MLCC), 680pF, ±5%, 50V, X7R, ±5%, SMD 0603; Manufacturer: YAGEO; Manufacturer Part Number: CC0603JRX7R9BB681
footprint CAP-0603 (0603 (1608M) Capacitor)
pins: 1, 2

## CC0603KRNPO9BN100
designator C?  Capacitance: 10pF  (hidden comment: *)
Capacitor, Ceramic (MLCC), 10pF, ±10%, 50V, NP0, ±10%, SMD 0603; Manufacturer: YAGEO; Manufacturer Part Number: CC0603KRNPO9BN100
footprint CAP-0603 (0603 (1608M) Capacitor)
pins: 1, 2

## CC0603KRNPO9BN220
designator C?  Capacitance: 22pF  (hidden comment: *)
Capacitor, Ceramic (MLCC), 22pF, ±10%, 50V, NP0, ±10%, SMD 0603; Manufacturer: YAGEO; Manufacturer Part Number: CC0603KRNPO9BN220
footprint CAP-0603 (0603 (1608M) Capacitor)
pins: 1, 2

## CC0603KRNPO9BN221
designator C?  Capacitance: 220pF  (hidden comment: *)
Capacitor, Ceramic (MLCC), 220pF, ±10%, 50V, NP0, ±10%, SMD 0603; Manufacturer: YAGEO; Manufacturer Part Number: CC0603KRNPO9BN221
footprint CAP-0603 (0603 (1608M) Capacitor)
pins: 1, 2

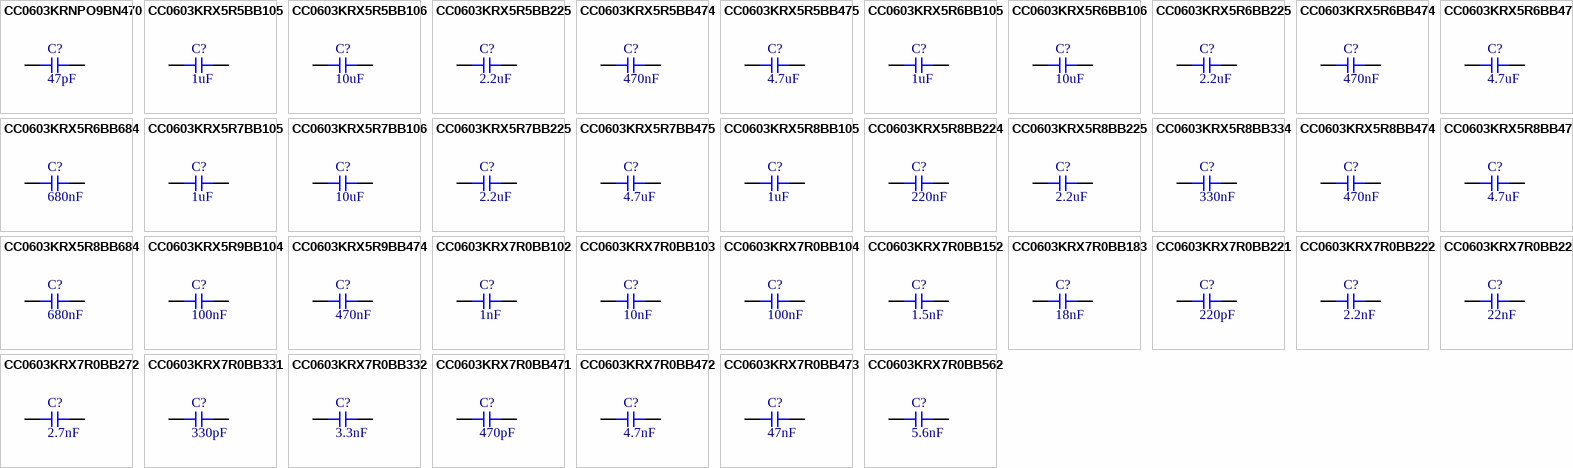
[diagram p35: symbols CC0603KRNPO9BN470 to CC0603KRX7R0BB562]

## CC0603KRNPO9BN470
designator C?  Capacitance: 47pF  (hidden comment: *)
Capacitor, Ceramic (MLCC), 47pF, ±10%, 50V, NP0, ±10%, SMD 0603; Manufacturer: YAGEO; Manufacturer Part Number: CC0603KRNPO9BN470
footprint CAP-0603 (0603 (1608M) Capacitor)
pins: 1, 2

## CC0603KRX5R5BB105
designator C?  Capacitance: 1uF  (hidden comment: *)
Capacitor, Ceramic (MLCC), 1uF, ±10%, 6.3V, X5R, ±10%, SMD 0603; Manufacturer: YAGEO; Manufacturer Part Number: CC0603KRX5R5BB105
footprint CAP-0603 (0603 (1608M) Capacitor)
pins: 1, 2

## CC0603KRX5R5BB106
designator C?  Capacitance: 10uF  (hidden comment: *)
Capacitor, Ceramic (MLCC), 10uF, ±10%, 6.3V, X5R, ±10%, SMD 0603; Manufacturer: YAGEO; Manufacturer Part Number: CC0603KRX5R5BB106
footprint CAP-0603 (0603 (1608M) Capacitor)
pins: 1, 2

## CC0603KRX5R5BB225
designator C?  Capacitance: 2.2uF  (hidden comment: *)
Capacitor, Ceramic (MLCC), 2.2uF, ±10%, 6.3V, X5R, ±10%, SMD 0603; Manufacturer: YAGEO; Manufacturer Part Number: CC0603KRX5R5BB225
footprint CAP-0603 (0603 (1608M) Capacitor)
pins: 1, 2

## CC0603KRX5R5BB474
designator C?  Capacitance: 470nF  (hidden comment: *)
Capacitor, Ceramic (MLCC), 470nF, ±10%, 6.3V, X5R, ±10%, SMD 0603; Manufacturer: YAGEO; Manufacturer Part Number: CC0603KRX5R5BB474
footprint CAP-0603 (0603 (1608M) Capacitor)
pins: 1, 2

## CC0603KRX5R5BB475
designator C?  Capacitance: 4.7uF  (hidden comment: *)
Capacitor, Ceramic (MLCC), 4.7uF, ±10%, 6.3V, X5R, ±10%, SMD 0603; Manufacturer: YAGEO; Manufacturer Part Number: CC0603KRX5R5BB475
footprint CAP-0603 (0603 (1608M) Capacitor)
pins: 1, 2

## CC0603KRX5R6BB105
designator C?  Capacitance: 1uF  (hidden comment: *)
Capacitor, Ceramic (MLCC), 1uF, ±10%, 10V, X5R, ±10%, SMD 0603; Manufacturer: YAGEO; Manufacturer Part Number: CC0603KRX5R6BB105
footprint CAP-0603 (0603 (1608M) Capacitor)
pins: 1, 2

## CC0603KRX5R6BB106
designator C?  Capacitance: 10uF  (hidden comment: *)
Capacitor, Ceramic (MLCC), 10uF, ±10%, 10V, X5R, ±10%, SMD 0603; Manufacturer: YAGEO; Manufacturer Part Number: CC0603KRX5R6BB106
footprint CAP-0603 (0603 (1608M) Capacitor)
pins: 1, 2

## CC0603KRX5R6BB225
designator C?  Capacitance: 2.2uF  (hidden comment: *)
Capacitor, Ceramic (MLCC), 2.2uF, ±10%, 10V, X5R, ±10%, SMD 0603; Manufacturer: YAGEO; Manufacturer Part Number: CC0603KRX5R6BB225
footprint CAP-0603 (0603 (1608M) Capacitor)
pins: 1, 2

## CC0603KRX5R6BB474
designator C?  Capacitance: 470nF  (hidden comment: *)
Capacitor, Ceramic (MLCC), 470nF, ±10%, 10V, X5R, ±10%, SMD 0603; Manufacturer: YAGEO; Manufacturer Part Number: CC0603KRX5R6BB474
footprint CAP-0603 (0603 (1608M) Capacitor)
pins: 1, 2

## CC0603KRX5R6BB475
designator C?  Capacitance: 4.7uF  (hidden comment: *)
Capacitor, Ceramic (MLCC), 4.7uF, ±10%, 10V, X5R, ±10%, SMD 0603; Manufacturer: YAGEO; Manufacturer Part Number: CC0603KRX5R6BB475
footprint CAP-0603 (0603 (1608M) Capacitor)
pins: 1, 2

## CC0603KRX5R6BB684
designator C?  Capacitance: 680nF  (hidden comment: *)
Capacitor, Ceramic (MLCC), 680nF, ±10%, 10V, X5R, ±10%, SMD 0603; Manufacturer: YAGEO; Manufacturer Part Number: CC0603KRX5R6BB684
footprint CAP-0603 (0603 (1608M) Capacitor)
pins: 1, 2

## CC0603KRX5R7BB105
designator C?  Capacitance: 1uF  (hidden comment: *)
Capacitor, Ceramic (MLCC), 1uF, ±10%, 16V, X5R, ±10%, SMD 0603; Manufacturer: YAGEO; Manufacturer Part Number: CC0603KRX5R7BB105
footprint CAP-0603 (0603 (1608M) Capacitor)
pins: 1, 2

## CC0603KRX5R7BB106
designator C?  Capacitance: 10uF  (hidden comment: *)
Capacitor, Ceramic (MLCC), 10uF, ±10%, 16V, X5R, ±10%, SMD 0603; Manufacturer: YAGEO; Manufacturer Part Number: CC0603KRX5R7BB106
footprint CAP-0603 (0603 (1608M) Capacitor)
pins: 1, 2

## CC0603KRX5R7BB225
designator C?  Capacitance: 2.2uF  (hidden comment: *)
Capacitor, Ceramic (MLCC), 2.2uF, ±10%, 16V, X5R, ±10%, SMD 0603; Manufacturer: YAGEO; Manufacturer Part Number: CC0603KRX5R7BB225
footprint CAP-0603 (0603 (1608M) Capacitor)
pins: 1, 2

## CC0603KRX5R7BB475
designator C?  Capacitance: 4.7uF  (hidden comment: *)
Capacitor, Ceramic (MLCC), 4.7uF, ±10%, 16V, X5R, ±10%, SMD 0603; Manufacturer: YAGEO; Manufacturer Part Number: CC0603KRX5R7BB475
footprint CAP-0603 (0603 (1608M) Capacitor)
pins: 1, 2

## CC0603KRX5R8BB105
designator C?  Capacitance: 1uF  (hidden comment: *)
Capacitor, Ceramic (MLCC), 1uF, ±10%, 25V, X5R, ±10%, SMD 0603; Manufacturer: YAGEO; Manufacturer Part Number: CC0603KRX5R8BB105
footprint CAP-0603 (0603 (1608M) Capacitor)
pins: 1, 2

## CC0603KRX5R8BB224
designator C?  Capacitance: 220nF  (hidden comment: *)
Capacitor, Ceramic (MLCC), 220nF, ±10%, 25V, X5R, ±10%, SMD 0603; Manufacturer: YAGEO; Manufacturer Part Number: CC0603KRX5R8BB224
footprint CAP-0603 (0603 (1608M) Capacitor)
pins: 1, 2

## CC0603KRX5R8BB225
designator C?  Capacitance: 2.2uF  (hidden comment: *)
Capacitor, Ceramic (MLCC), 2.2uF, ±10%, 25V, X5R, ±10%, SMD 0603; Manufacturer: YAGEO; Manufacturer Part Number: CC0603KRX5R8BB225
footprint CAP-0603 (0603 (1608M) Capacitor)
pins: 1, 2

## CC0603KRX5R8BB334
designator C?  Capacitance: 330nF  (hidden comment: *)
Capacitor, Ceramic (MLCC), 330nF, ±10%, 25V, X5R, ±10%, SMD 0603; Manufacturer: YAGEO; Manufacturer Part Number: CC0603KRX5R8BB334
footprint CAP-0603 (0603 (1608M) Capacitor)
pins: 1, 2

## CC0603KRX5R8BB474
designator C?  Capacitance: 470nF  (hidden comment: *)
Capacitor, Ceramic (MLCC), 470nF, ±10%, 25V, X5R, ±10%, SMD 0603; Manufacturer: YAGEO; Manufacturer Part Number: CC0603KRX5R8BB474
footprint CAP-0603 (0603 (1608M) Capacitor)
pins: 1, 2

## CC0603KRX5R8BB475
designator C?  Capacitance: 4.7uF  (hidden comment: *)
Capacitor, Ceramic (MLCC), 4.7uF, ±10%, 25V, X5R, ±10%, SMD 0603; Manufacturer: YAGEO; Manufacturer Part Number: CC0603KRX5R8BB475
footprint CAP-0603 (0603 (1608M) Capacitor)
pins: 1, 2

## CC0603KRX5R8BB684
designator C?  Capacitance: 680nF  (hidden comment: *)
Capacitor, Ceramic (MLCC), 680nF, ±10%, 25V, X5R, ±10%, SMD 0603; Manufacturer: YAGEO; Manufacturer Part Number: CC0603KRX5R8BB684
footprint CAP-0603 (0603 (1608M) Capacitor)
pins: 1, 2

## CC0603KRX5R9BB104
designator C?  Capacitance: 100nF  (hidden comment: *)
Capacitor, Ceramic (MLCC), 100nF, ±10%, 50V, X5R, ±10%, SMD 0603; Manufacturer: YAGEO; Manufacturer Part Number: CC0603KRX5R9BB104
footprint CAP-0603 (0603 (1608M) Capacitor)
pins: 1, 2

## CC0603KRX5R9BB474
designator C?  Capacitance: 470nF  (hidden comment: *)
Capacitor, Ceramic (MLCC), 470nF, ±10%, 50V, X5R, ±10%, SMD 0603; Manufacturer: YAGEO; Manufacturer Part Number: CC0603KRX5R9BB474
footprint CAP-0603 (0603 (1608M) Capacitor)
pins: 1, 2

## CC0603KRX7R0BB102
designator C?  Capacitance: 1nF  (hidden comment: *)
Capacitor, Ceramic (MLCC), 1nF, ±10%, 100V, X7R, ±10%, SMD 0603; Manufacturer: YAGEO; Manufacturer Part Number: CC0603KRX7R0BB102
footprint CAP-0603 (0603 (1608M) Capacitor)
pins: 1, 2

## CC0603KRX7R0BB103
designator C?  Capacitance: 10nF  (hidden comment: *)
Capacitor, Ceramic (MLCC), 10nF, ±10%, 100V, X7R, ±10%, SMD 0603; Manufacturer: YAGEO; Manufacturer Part Number: CC0603KRX7R0BB103
footprint CAP-0603 (0603 (1608M) Capacitor)
pins: 1, 2

## CC0603KRX7R0BB104
designator C?  Capacitance: 100nF  (hidden comment: *)
Capacitor, Ceramic (MLCC), 100nF, ±10%, 100V, X7R, ±10%, SMD 0603; Manufacturer: YAGEO; Manufacturer Part Number: CC0603KRX7R0BB104
footprint CAP-0603 (0603 (1608M) Capacitor)
pins: 1, 2

## CC0603KRX7R0BB152
designator C?  Capacitance: 1.5nF  (hidden comment: *)
Capacitor, Ceramic (MLCC), 1.5nF, ±10%, 100V, X7R, ±10%, SMD 0603; Manufacturer: YAGEO; Manufacturer Part Number: CC0603KRX7R0BB152
footprint CAP-0603 (0603 (1608M) Capacitor)
pins: 1, 2

## CC0603KRX7R0BB183
designator C?  Capacitance: 18nF  (hidden comment: *)
Capacitor, Ceramic (MLCC), 18nF, ±10%, 100V, X7R, ±10%, SMD 0603; Manufacturer: YAGEO; Manufacturer Part Number: CC0603KRX7R0BB183
footprint CAP-0603 (0603 (1608M) Capacitor)
pins: 1, 2

## CC0603KRX7R0BB221
designator C?  Capacitance: 220pF  (hidden comment: *)
Capacitor, Ceramic (MLCC), 220pF, ±10%, 100V, X7R, ±10%, SMD 0603; Manufacturer: YAGEO; Manufacturer Part Number: CC0603KRX7R0BB221
footprint CAP-0603 (0603 (1608M) Capacitor)
pins: 1, 2

## CC0603KRX7R0BB222
designator C?  Capacitance: 2.2nF  (hidden comment: *)
Capacitor, Ceramic (MLCC), 2.2nF, ±10%, 100V, X7R, ±10%, SMD 0603; Manufacturer: YAGEO; Manufacturer Part Number: CC0603KRX7R0BB222
footprint CAP-0603 (0603 (1608M) Capacitor)
pins: 1, 2

## CC0603KRX7R0BB223
designator C?  Capacitance: 22nF  (hidden comment: *)
Capacitor, Ceramic (MLCC), 22nF, ±10%, 100V, X7R, ±10%, SMD 0603; Manufacturer: YAGEO; Manufacturer Part Number: CC0603KRX7R0BB223
footprint CAP-0603 (0603 (1608M) Capacitor)
pins: 1, 2

## CC0603KRX7R0BB272
designator C?  Capacitance: 2.7nF  (hidden comment: *)
Capacitor, Ceramic (MLCC), 2.7nF, ±10%, 100V, X7R, ±10%, SMD 0603; Manufacturer: YAGEO; Manufacturer Part Number: CC0603KRX7R0BB272
footprint CAP-0603 (0603 (1608M) Capacitor)
pins: 1, 2

## CC0603KRX7R0BB331
designator C?  Capacitance: 330pF  (hidden comment: *)
Capacitor, Ceramic (MLCC), 330pF, ±10%, 100V, X7R, ±10%, SMD 0603; Manufacturer: YAGEO; Manufacturer Part Number: CC0603KRX7R0BB331
footprint CAP-0603 (0603 (1608M) Capacitor)
pins: 1, 2

## CC0603KRX7R0BB332
designator C?  Capacitance: 3.3nF  (hidden comment: *)
Capacitor, Ceramic (MLCC), 3.3nF, ±10%, 100V, X7R, ±10%, SMD 0603; Manufacturer: YAGEO; Manufacturer Part Number: CC0603KRX7R0BB332
footprint CAP-0603 (0603 (1608M) Capacitor)
pins: 1, 2

## CC0603KRX7R0BB471
designator C?  Capacitance: 470pF  (hidden comment: *)
Capacitor, Ceramic (MLCC), 470pF, ±10%, 100V, X7R, ±10%, SMD 0603; Manufacturer: YAGEO; Manufacturer Part Number: CC0603KRX7R0BB471
footprint CAP-0603 (0603 (1608M) Capacitor)
pins: 1, 2

## CC0603KRX7R0BB472
designator C?  Capacitance: 4.7nF  (hidden comment: *)
Capacitor, Ceramic (MLCC), 4.7nF, ±10%, 100V, X7R, ±10%, SMD 0603; Manufacturer: YAGEO; Manufacturer Part Number: CC0603KRX7R0BB472
footprint CAP-0603 (0603 (1608M) Capacitor)
pins: 1, 2

## CC0603KRX7R0BB473
designator C?  Capacitance: 47nF  (hidden comment: *)
Capacitor, Ceramic (MLCC), 47nF, ±10%, 100V, X7R, ±10%, SMD 0603; Manufacturer: YAGEO; Manufacturer Part Number: CC0603KRX7R0BB473
footprint CAP-0603 (0603 (1608M) Capacitor)
pins: 1, 2

## CC0603KRX7R0BB562
designator C?  Capacitance: 5.6nF  (hidden comment: *)
Capacitor, Ceramic (MLCC), 5.6nF, ±10%, 100V, X7R, ±10%, SMD 0603; Manufacturer: YAGEO; Manufacturer Part Number: CC0603KRX7R0BB562
footprint CAP-0603 (0603 (1608M) Capacitor)
pins: 1, 2

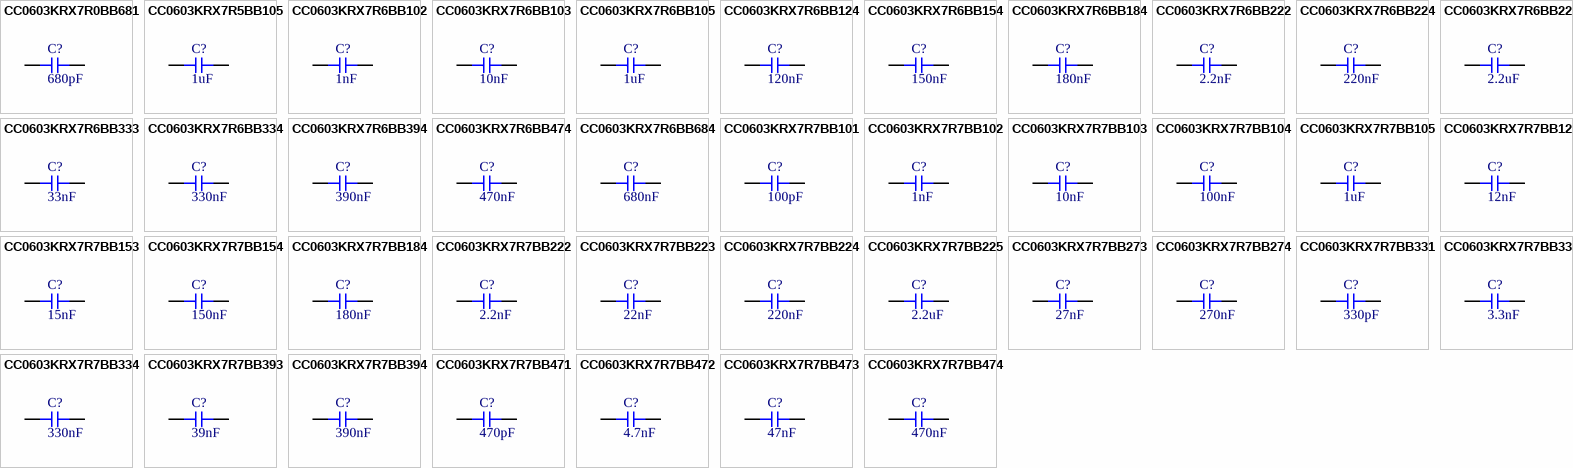
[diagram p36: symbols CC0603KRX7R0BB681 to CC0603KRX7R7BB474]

## CC0603KRX7R0BB681
designator C?  Capacitance: 680pF  (hidden comment: *)
Capacitor, Ceramic (MLCC), 680pF, ±10%, 100V, X7R, ±10%, SMD 0603; Manufacturer: YAGEO; Manufacturer Part Number: CC0603KRX7R0BB681
footprint CAP-0603 (0603 (1608M) Capacitor)
pins: 1, 2

## CC0603KRX7R5BB105
designator C?  Capacitance: 1uF  (hidden comment: *)
Capacitor, Ceramic (MLCC), 1uF, ±10%, 6.3V, X7R, ±10%, SMD 0603; Manufacturer: YAGEO; Manufacturer Part Number: CC0603KRX7R5BB105
footprint CAP-0603 (0603 (1608M) Capacitor)
pins: 1, 2

## CC0603KRX7R6BB102
designator C?  Capacitance: 1nF  (hidden comment: *)
Capacitor, Ceramic (MLCC), 1nF, ±10%, 10V, X7R, ±10%, SMD 0603; Manufacturer: YAGEO; Manufacturer Part Number: CC0603KRX7R6BB102
footprint CAP-0603 (0603 (1608M) Capacitor)
pins: 1, 2

## CC0603KRX7R6BB103
designator C?  Capacitance: 10nF  (hidden comment: *)
Capacitor, Ceramic (MLCC), 10nF, ±10%, 10V, X7R, ±10%, SMD 0603; Manufacturer: YAGEO; Manufacturer Part Number: CC0603KRX7R6BB103
footprint CAP-0603 (0603 (1608M) Capacitor)
pins: 1, 2

## CC0603KRX7R6BB105
designator C?  Capacitance: 1uF  (hidden comment: *)
Capacitor, Ceramic (MLCC), 1uF, ±10%, 10V, X7R, ±10%, SMD 0603; Manufacturer: YAGEO; Manufacturer Part Number: CC0603KRX7R6BB105
footprint CAP-0603 (0603 (1608M) Capacitor)
pins: 1, 2

## CC0603KRX7R6BB124
designator C?  Capacitance: 120nF  (hidden comment: *)
Capacitor, Ceramic (MLCC), 120nF, ±10%, 10V, X7R, ±10%, SMD 0603; Manufacturer: YAGEO; Manufacturer Part Number: CC0603KRX7R6BB124
footprint CAP-0603 (0603 (1608M) Capacitor)
pins: 1, 2

## CC0603KRX7R6BB154
designator C?  Capacitance: 150nF  (hidden comment: *)
Capacitor, Ceramic (MLCC), 150nF, ±10%, 10V, X7R, ±10%, SMD 0603; Manufacturer: YAGEO; Manufacturer Part Number: CC0603KRX7R6BB154
footprint CAP-0603 (0603 (1608M) Capacitor)
pins: 1, 2

## CC0603KRX7R6BB184
designator C?  Capacitance: 180nF  (hidden comment: *)
Capacitor, Ceramic (MLCC), 180nF, ±10%, 10V, X7R, ±10%, SMD 0603; Manufacturer: YAGEO; Manufacturer Part Number: CC0603KRX7R6BB184
footprint CAP-0603 (0603 (1608M) Capacitor)
pins: 1, 2

## CC0603KRX7R6BB222
designator C?  Capacitance: 2.2nF  (hidden comment: *)
Capacitor, Ceramic (MLCC), 2.2nF, ±10%, 10V, X7R, ±10%, SMD 0603; Manufacturer: YAGEO; Manufacturer Part Number: CC0603KRX7R6BB222
footprint CAP-0603 (0603 (1608M) Capacitor)
pins: 1, 2

## CC0603KRX7R6BB224
designator C?  Capacitance: 220nF  (hidden comment: *)
Capacitor, Ceramic (MLCC), 220nF, ±10%, 10V, X7R, ±10%, SMD 0603; Manufacturer: YAGEO; Manufacturer Part Number: CC0603KRX7R6BB224
footprint CAP-0603 (0603 (1608M) Capacitor)
pins: 1, 2

## CC0603KRX7R6BB225
designator C?  Capacitance: 2.2uF  (hidden comment: *)
Capacitor, Ceramic (MLCC), 2.2uF, ±10%, 10V, X7R, ±10%, SMD 0603; Manufacturer: YAGEO; Manufacturer Part Number: CC0603KRX7R6BB225
footprint CAP-0603 (0603 (1608M) Capacitor)
pins: 1, 2

## CC0603KRX7R6BB333
designator C?  Capacitance: 33nF  (hidden comment: *)
Capacitor, Ceramic (MLCC), 33nF, ±10%, 10V, X7R, ±10%, SMD 0603; Manufacturer: YAGEO; Manufacturer Part Number: CC0603KRX7R6BB333
footprint CAP-0603 (0603 (1608M) Capacitor)
pins: 1, 2

## CC0603KRX7R6BB334
designator C?  Capacitance: 330nF  (hidden comment: *)
Capacitor, Ceramic (MLCC), 330nF, ±10%, 10V, X7R, ±10%, SMD 0603; Manufacturer: YAGEO; Manufacturer Part Number: CC0603KRX7R6BB334
footprint CAP-0603 (0603 (1608M) Capacitor)
pins: 1, 2

## CC0603KRX7R6BB394
designator C?  Capacitance: 390nF  (hidden comment: *)
Capacitor, Ceramic (MLCC), 390nF, ±10%, 10V, X7R, ±10%, SMD 0603; Manufacturer: YAGEO; Manufacturer Part Number: CC0603KRX7R6BB394
footprint CAP-0603 (0603 (1608M) Capacitor)
pins: 1, 2

## CC0603KRX7R6BB474
designator C?  Capacitance: 470nF  (hidden comment: *)
Capacitor, Ceramic (MLCC), 470nF, ±10%, 10V, X7R, ±10%, SMD 0603; Manufacturer: YAGEO; Manufacturer Part Number: CC0603KRX7R6BB474
footprint CAP-0603 (0603 (1608M) Capacitor)
pins: 1, 2

## CC0603KRX7R6BB684
designator C?  Capacitance: 680nF  (hidden comment: *)
Capacitor, Ceramic (MLCC), 680nF, ±10%, 10V, X7R, ±10%, SMD 0603; Manufacturer: YAGEO; Manufacturer Part Number: CC0603KRX7R6BB684
footprint CAP-0603 (0603 (1608M) Capacitor)
pins: 1, 2

## CC0603KRX7R7BB101
designator C?  Capacitance: 100pF  (hidden comment: *)
Capacitor, Ceramic (MLCC), 100pF, ±10%, 16V, X7R, ±10%, SMD 0603; Manufacturer: YAGEO; Manufacturer Part Number: CC0603KRX7R7BB101
footprint CAP-0603 (0603 (1608M) Capacitor)
pins: 1, 2

## CC0603KRX7R7BB102
designator C?  Capacitance: 1nF  (hidden comment: *)
Capacitor, Ceramic (MLCC), 1nF, ±10%, 16V, X7R, ±10%, SMD 0603; Manufacturer: YAGEO; Manufacturer Part Number: CC0603KRX7R7BB102
footprint CAP-0603 (0603 (1608M) Capacitor)
pins: 1, 2

## CC0603KRX7R7BB103
designator C?  Capacitance: 10nF  (hidden comment: *)
Capacitor, Ceramic (MLCC), 10nF, ±10%, 16V, X7R, ±10%, SMD 0603; Manufacturer: YAGEO; Manufacturer Part Number: CC0603KRX7R7BB103
footprint CAP-0603 (0603 (1608M) Capacitor)
pins: 1, 2

## CC0603KRX7R7BB104
designator C?  Capacitance: 100nF  (hidden comment: *)
Capacitor, Ceramic (MLCC), 100nF, ±10%, 16V, X7R, ±10%, SMD 0603; Manufacturer: YAGEO; Manufacturer Part Number: CC0603KRX7R7BB104
footprint CAP-0603 (0603 (1608M) Capacitor)
pins: 1, 2

## CC0603KRX7R7BB105
designator C?  Capacitance: 1uF  (hidden comment: *)
Capacitor, Ceramic (MLCC), 1uF, ±10%, 16V, X7R, ±10%, SMD 0603; Manufacturer: YAGEO; Manufacturer Part Number: CC0603KRX7R7BB105
footprint CAP-0603 (0603 (1608M) Capacitor)
pins: 1, 2

## CC0603KRX7R7BB123
designator C?  Capacitance: 12nF  (hidden comment: *)
Capacitor, Ceramic (MLCC), 12nF, ±10%, 16V, X7R, ±10%, SMD 0603; Manufacturer: YAGEO; Manufacturer Part Number: CC0603KRX7R7BB123
footprint CAP-0603 (0603 (1608M) Capacitor)
pins: 1, 2

## CC0603KRX7R7BB153
designator C?  Capacitance: 15nF  (hidden comment: *)
Capacitor, Ceramic (MLCC), 15nF, ±10%, 16V, X7R, ±10%, SMD 0603; Manufacturer: YAGEO; Manufacturer Part Number: CC0603KRX7R7BB153
footprint CAP-0603 (0603 (1608M) Capacitor)
pins: 1, 2

## CC0603KRX7R7BB154
designator C?  Capacitance: 150nF  (hidden comment: *)
Capacitor, Ceramic (MLCC), 150nF, ±10%, 16V, X7R, ±10%, SMD 0603; Manufacturer: YAGEO; Manufacturer Part Number: CC0603KRX7R7BB154
footprint CAP-0603 (0603 (1608M) Capacitor)
pins: 1, 2

## CC0603KRX7R7BB184
designator C?  Capacitance: 180nF  (hidden comment: *)
Capacitor, Ceramic (MLCC), 180nF, ±10%, 16V, X7R, ±10%, SMD 0603; Manufacturer: YAGEO; Manufacturer Part Number: CC0603KRX7R7BB184
footprint CAP-0603 (0603 (1608M) Capacitor)
pins: 1, 2

## CC0603KRX7R7BB222
designator C?  Capacitance: 2.2nF  (hidden comment: *)
Capacitor, Ceramic (MLCC), 2.2nF, ±10%, 16V, X7R, ±10%, SMD 0603; Manufacturer: YAGEO; Manufacturer Part Number: CC0603KRX7R7BB222
footprint CAP-0603 (0603 (1608M) Capacitor)
pins: 1, 2

## CC0603KRX7R7BB223
designator C?  Capacitance: 22nF  (hidden comment: *)
Capacitor, Ceramic (MLCC), 22nF, ±10%, 16V, X7R, ±10%, SMD 0603; Manufacturer: YAGEO; Manufacturer Part Number: CC0603KRX7R7BB223
footprint CAP-0603 (0603 (1608M) Capacitor)
pins: 1, 2

## CC0603KRX7R7BB224
designator C?  Capacitance: 220nF  (hidden comment: *)
Capacitor, Ceramic (MLCC), 220nF, ±10%, 16V, X7R, ±10%, SMD 0603; Manufacturer: YAGEO; Manufacturer Part Number: CC0603KRX7R7BB224
footprint CAP-0603 (0603 (1608M) Capacitor)
pins: 1, 2

## CC0603KRX7R7BB225
designator C?  Capacitance: 2.2uF  (hidden comment: *)
Capacitor, Ceramic (MLCC), 2.2uF, ±10%, 16V, X7R, ±10%, SMD 0603; Manufacturer: YAGEO; Manufacturer Part Number: CC0603KRX7R7BB225
footprint CAP-0603 (0603 (1608M) Capacitor)
pins: 1, 2

## CC0603KRX7R7BB273
designator C?  Capacitance: 27nF  (hidden comment: *)
Capacitor, Ceramic (MLCC), 27nF, ±10%, 16V, X7R, ±10%, SMD 0603; Manufacturer: YAGEO; Manufacturer Part Number: CC0603KRX7R7BB273
footprint CAP-0603 (0603 (1608M) Capacitor)
pins: 1, 2

## CC0603KRX7R7BB274
designator C?  Capacitance: 270nF  (hidden comment: *)
Capacitor, Ceramic (MLCC), 270nF, ±10%, 16V, X7R, ±10%, SMD 0603; Manufacturer: YAGEO; Manufacturer Part Number: CC0603KRX7R7BB274
footprint CAP-0603 (0603 (1608M) Capacitor)
pins: 1, 2

## CC0603KRX7R7BB331
designator C?  Capacitance: 330pF  (hidden comment: *)
Capacitor, Ceramic (MLCC), 330pF, ±10%, 16V, X7R, ±10%, SMD 0603; Manufacturer: YAGEO; Manufacturer Part Number: CC0603KRX7R7BB331
footprint CAP-0603 (0603 (1608M) Capacitor)
pins: 1, 2

## CC0603KRX7R7BB332
designator C?  Capacitance: 3.3nF  (hidden comment: *)
Capacitor, Ceramic (MLCC), 3.3nF, ±10%, 16V, X7R, ±10%, SMD 0603; Manufacturer: YAGEO; Manufacturer Part Number: CC0603KRX7R7BB332
footprint CAP-0603 (0603 (1608M) Capacitor)
pins: 1, 2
